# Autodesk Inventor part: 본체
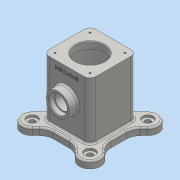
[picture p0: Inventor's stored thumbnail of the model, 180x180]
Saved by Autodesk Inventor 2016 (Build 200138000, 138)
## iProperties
Created: 2019-11
Part Number: 본체
Material: 일반
Document SubType Name: Modeling
Designer: user
Density: 1 g/cm^3
Appearance: 기본값
Author: user
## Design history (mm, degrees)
sketch "스케치1"
  geometry: L1 (-49, -49)-(49, -49); L2 (49, -49)-(49, 49); L3 (49, 49)-(-49, 49); L4 (-49, 49)-(-49, -49); L5 (-49, -49)-(49, 49); L6 (49, -49)-(-49, 49); L7 (-49.497, -49.497)-(49.497, 49.497); L8 (-36.77, -62.225)-(62.225, 36.77); L9 (36.77, 62.225)-(-62.225, -36.77); L10 (49.497, -49.497)-(-49.497, 49.497); L11 (62.225, -36.77)-(-36.77, 62.225); L12 (-62.225, 36.77)-(36.77, -62.225); A1 r 18 centre (-49.497, -49.497) between (-62.225, -36.77) and (-36.77, -62.225); A2 r 18 centre (49.497, 49.497) between (62.225, 36.77) and (36.77, 62.225); A3 r 18 centre (49.497, -49.497) between (36.77, -62.225) and (62.225, -36.77); A4 r 18 centre (-49.497, 49.497) between (-36.77, 62.225) and (-62.225, 36.77); A5 r 70 centre (0, 0) between (-49.497, 49.497) and (49.497, 49.497); 1 further point
  constraints: 28 end point, 10 point on circle, 8 tangent, 5 centre point, 4 midpoint, 4 parallel, 2 point on line, 1 coincident, 1 horizontal, 1 perpendicular
  dimensions: "d0" = 98 distance of L3.end L2.end; "d1" = 98 distance of L2.end L1.end; "d2" = 18 radius of A4; "d3" = 18 radius of A2; "d4" = 140 diameter of A5
extrude "돌출1" new body sketch "스케치1" distance "d5" = 12; taper "d6" = 0 deg
sketch "스케치2"
  geometry: L1 (-40, -40)-(40, -40); L2 (40, -40)-(40, 40); L3 (40, 40)-(-40, 40); L4 (-40, 40)-(-40, -40); L5 (-40, -40)-(40, 40); L6 (40, -40)-(-40, 40); 1 further point
  constraints: 12 end point, 2 midpoint, 2 parallel, 1 horizontal, 1 perpendicular
  dimensions: "d7" = 80 distance of L3.end L2.end; "d8" = 80 distance of L2.end L1.end
extrude "돌출2" join sketch "스케치2" distance "d9" = 98; taper "d10" = 0 deg
node "작업 평면1"
sketch "스케치4"
  geometry: C1 r 20 at (0, 61); 1 further point
  constraints: 1 centre point, 1 vertical alignment
  dimensions: "d14" = 40 diameter of C1; "d15" = 61 distance of point (0, 0) C1.centre
extrude "돌출3" join sketch "스케치4" stored distance "d16" = 98; taper "d17" = 0 deg
sketch "스케치5"
  geometry: C1 r 25 at (0, 0); 1 further point
  constraints: 1 centre point, 1 coincident
  dimensions: "d18" = 50 diameter of C1
extrude "돌출4" cut sketch "스케치5" distance "d19" = 12; taper "d20" = 0 deg
node "작업 평면2"
sketch "스케치6"
  geometry: C1 r 35 at (0, 0); 1 further point
  constraints: 1 centre point, 1 coincident
  dimensions: "d22" = 70 diameter of C1
extrude "돌출5" cut sketch "스케치6" distance "d23" = 86; taper "d24" = 0 deg
sketch "스케치7"
  geometry: C1 r 20 at (0, 0) reference; 2 further points
  constraints: 1 coincident
hole "구멍1" sketch "스케치7" at (0, 0) diameter "d25" = 25; stored, may be unused: countersink angle "d29" = 90 deg, drill point angle "d31" = 118 deg; dims "d26" = 6, "d27" = 30, "d28" = 8, "d30" = 46
sketch "스케치8"
  geometry: L1 (-30, -30)-(30, -30); L2 (30, -30)-(30, 30); L3 (30, 30)-(-30, 30); L4 (-30, 30)-(-30, -30); L5 (-30, -30)-(30, 30); L6 (30, -30)-(-30, 30); 2 further points
  constraints: 12 end point, 2 midpoint, 2 parallel, 1 coincident, 1 horizontal, 1 perpendicular
  dimensions: "d32" = 60 distance of L3.end L2.end; "d33" = 60 distance of L2.end L1.end
hole "구멍2" sketch "스케치8" at (30, 30) diameter "d34" = 3.242; stored, may be unused: countersink angle "d38" = 90 deg, drill point angle "d40" = 118 deg; dims "d35" = 8, "d36" = 30, "d37" = 8, "d39" = 10
node "작업 평면3"
sketch "스케치9"
  geometry: L1 (0, 0)-(-49.497, 49.497); L2 (49, -23.544)-(49, 23.544) reference; 1 further point
  constraints: 2 end point, 1 coincident
  dimensions: "d48" = 70 distance of L1.start L1.end; "d49" = 45 deg angle of L2 L1
hole "구멍3" sketch "스케치9" at (-49.497, 49.497) diameter "d50" = 10; stored, may be unused: countersink angle "d54" = 90 deg, drill point angle "d56" = 118 deg; dims "d51" = 8, "d52" = 18, "d53" = 4, "d55" = 10
fillet "모깎기1" dims "d60" = 10
fillet "모깎기2" dims "d61" = 3
fillet "모깎기3" dims "d62" = 25
fillet "모깎기4" dims "d63" = 3
chamfer "모따기1" distance "d64" = 1; stored, may be unused: second distance "d65" = 2, angle "d66" = 45 deg
fillet "모깎기5" dims "d67" = 3
fillet "모깎기6" dims "d68" = 3
sketch "스케치10"
  geometry: L1 (0, 0)-(60, 0) reference; L2 (16.811, -110)-(43.189, -110) reference; 3 further points
  constraints: 1 midpoint, 1 vertical alignment, 1 other
  dimensions: "d69" = 10 distance from line of L1 point (30, -10)
feature "엠보싱1" sketch "스케치10" dims "d0" = 98, "d1" = 98, "d2" = 18, "d3" = 18, "d4" = 140, "d70" = 0.3, "d71" = 0
node "솔리드1"
mirror "대칭1"
pattern_linear "직사각형 패턴1" dims "d43" = 60
mirror "대칭2"
pattern_circular "원형 패턴1" dims angle "d58" = 360 deg
other parameters: "d13" = -55, "d21" = 55, "d47" = 55
